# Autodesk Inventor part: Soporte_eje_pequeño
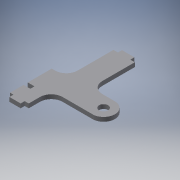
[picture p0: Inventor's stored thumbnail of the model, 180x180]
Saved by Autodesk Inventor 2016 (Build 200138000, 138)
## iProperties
Created: 2017-06
Part Number: Soporte_eje_pequeño
Material: Generic
Document SubType Name: Modeling
Designer: laboratorioesan
Density: 1 g/cm^3
Appearance: Default
Author: laboratorioesan
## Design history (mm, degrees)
sketch "Sketch1"
  geometry: L1 (0, 0)-(-50, 0) reference; L2 (0, 0)-(0, 18.5) reference; L3 (-50, 18.5)-(0, 18.5) reference; L4 (-50, 0)-(-50, 18.5) reference; L5 (75, 412.5)-(20, 412.5) reference; L6 (75, 412.5)-(75, 431) reference; L7 (20, 431)-(75, 431) reference; L8 (20, 412.5)-(20, 431) reference; L9 (75, 412.5)-(20, 412.5); L10 (20, 412.5)-(20, 430.5); L11 (20, 430.5)-(75, 430.5); L12 (75, 430.5)-(75, 412.5); L13 (-40.1, 268.5)-(200.774, 167.998); L14 (95, 872.5)-(95, 382.5) reference; L15 (75, 412.5)-(95, 412.5); L16 (95, 412.5)-(95, 217.998); L17 (95, 217.998)-(200.774, 217.998); L18 (207.839, 118.5)-(18, 118.5); L19 (0, 18.5)-(-50, 18.5); L20 (-50, 18.5)-(-50, 0.5); L21 (-50, 0.5)-(0, 0.5); L22 (0, 0.5)-(0, 18.5); L23 (0, 18.5)-(18, 18.5); L24 (18, 18.5)-(18, 118.5); L25 (20, 412.5)-(0, 412.5); L26 (0, 412.5)-(0, 203.465); L27 (0, 203.465)-(-65, 203.465); L28 (-65, 203.465)-(-65, 18.5); L29 (-65, 18.5)-(-50, 18.5); L30 (237.066, 118.5)-(-65, 118.5) reference; C1 r 24.9 at (-40.1, 268.5) reference; C2 r 20 at (200.774, 167.998); A1 r 50 centre (200.774, 167.998) between (207.839, 118.5) and (200.774, 217.998)
  constraints: 40 end point, 7 perpendicular, 6 horizontal, 4 parallel, 3 point on line, 2 centre point, 2 coincident, 2 point on circle, 1 horizontal alignment, 1 tangent, 1 vertical
  dimensions: "d0" = 18 distance of L9.end L10.end; "d1" = 261 distance of L13.start L13.end; "d2" = 40 diameter of C2; "d3" = 20 distance of L5.start L15.end; "d4" = 100 diameter of A1; "d5" = 18 distance of L20.end L19.end; "d6" = 18 distance of L2.end L23.end; "d7" = 20 distance of L9.end L25.end
extrude "Extrusion1" new body sketch "Sketch1" distance "d8" = 18.5; taper "d9" = 0 deg
fillet "Fillet1" dims "d10" = 50
sketch "Sketch2"
  geometry: L1 (75, 412.5)-(75, 430.5) reference; L2 (75, 430.5)-(20, 430.5) reference; L3 (20, 430.5)-(20, 412.5) reference; L4 (20, 412.5)-(0, 412.5) reference; L5 (0, 412.5)-(0, 253.465) reference; L6 (-50, 203.465)-(-65, 203.465) reference; L7 (-65, 203.465)-(-65, 18.5) reference; L8 (-65, 18.5)-(-50, 18.5) reference; L9 (-50, 18.5)-(-50, 0.5) reference; L10 (-50, 0.5)-(0, 0.5) reference; L11 (0, 0.5)-(0, 18.5) reference; L12 (0, 18.5)-(18, 18.5) reference; L13 (18, 18.5)-(18, 68.5) reference; L14 (68, 118.5)-(207.839, 118.5) reference; L15 (200.774, 217.998)-(145, 217.998) reference; L16 (95, 267.998)-(95, 412.5) reference; L17 (95, 412.5)-(75, 412.5) reference; L18 (-65, 97)-(-35, 97); L19 (-35, 97)-(-35, 78.5); L20 (-35, 78.5)-(-65, 78.5); L21 (-65, 78.5)-(-65, 97); C1 r 20 at (200.774, 167.998) reference; A1 r 50 centre (-50, 253.465) between (-50, 203.465) and (0, 253.465) reference; A2 r 50 centre (68, 68.5) between (68, 118.5) and (18, 68.5) reference; A3 r 50 centre (200.774, 167.998) between (207.839, 118.5) and (200.774, 217.998) reference; A4 r 50 centre (145, 267.998) between (95, 267.998) and (145, 217.998) reference; 1 further point
  constraints: 8 end point, 2 parallel, 1 horizontal, 1 perpendicular, 1 point on line
  dimensions: "d11" = 30 distance of L19.end L20.end; "d12" = 18.5 distance of L18.end L19.end; "d13" = 60 vertical distance of L7.end L19.end
extrude "Extrusion2" cut sketch "Sketch2" distance "d14" = 18.5; taper "d15" = 0 deg
body "Solid1"
node "Reference1"
node "Reference2"
node "Reference3"
node "Reference4"
node "Reference5"
node "Projected Loop1"
